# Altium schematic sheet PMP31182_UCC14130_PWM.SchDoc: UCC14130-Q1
size A3
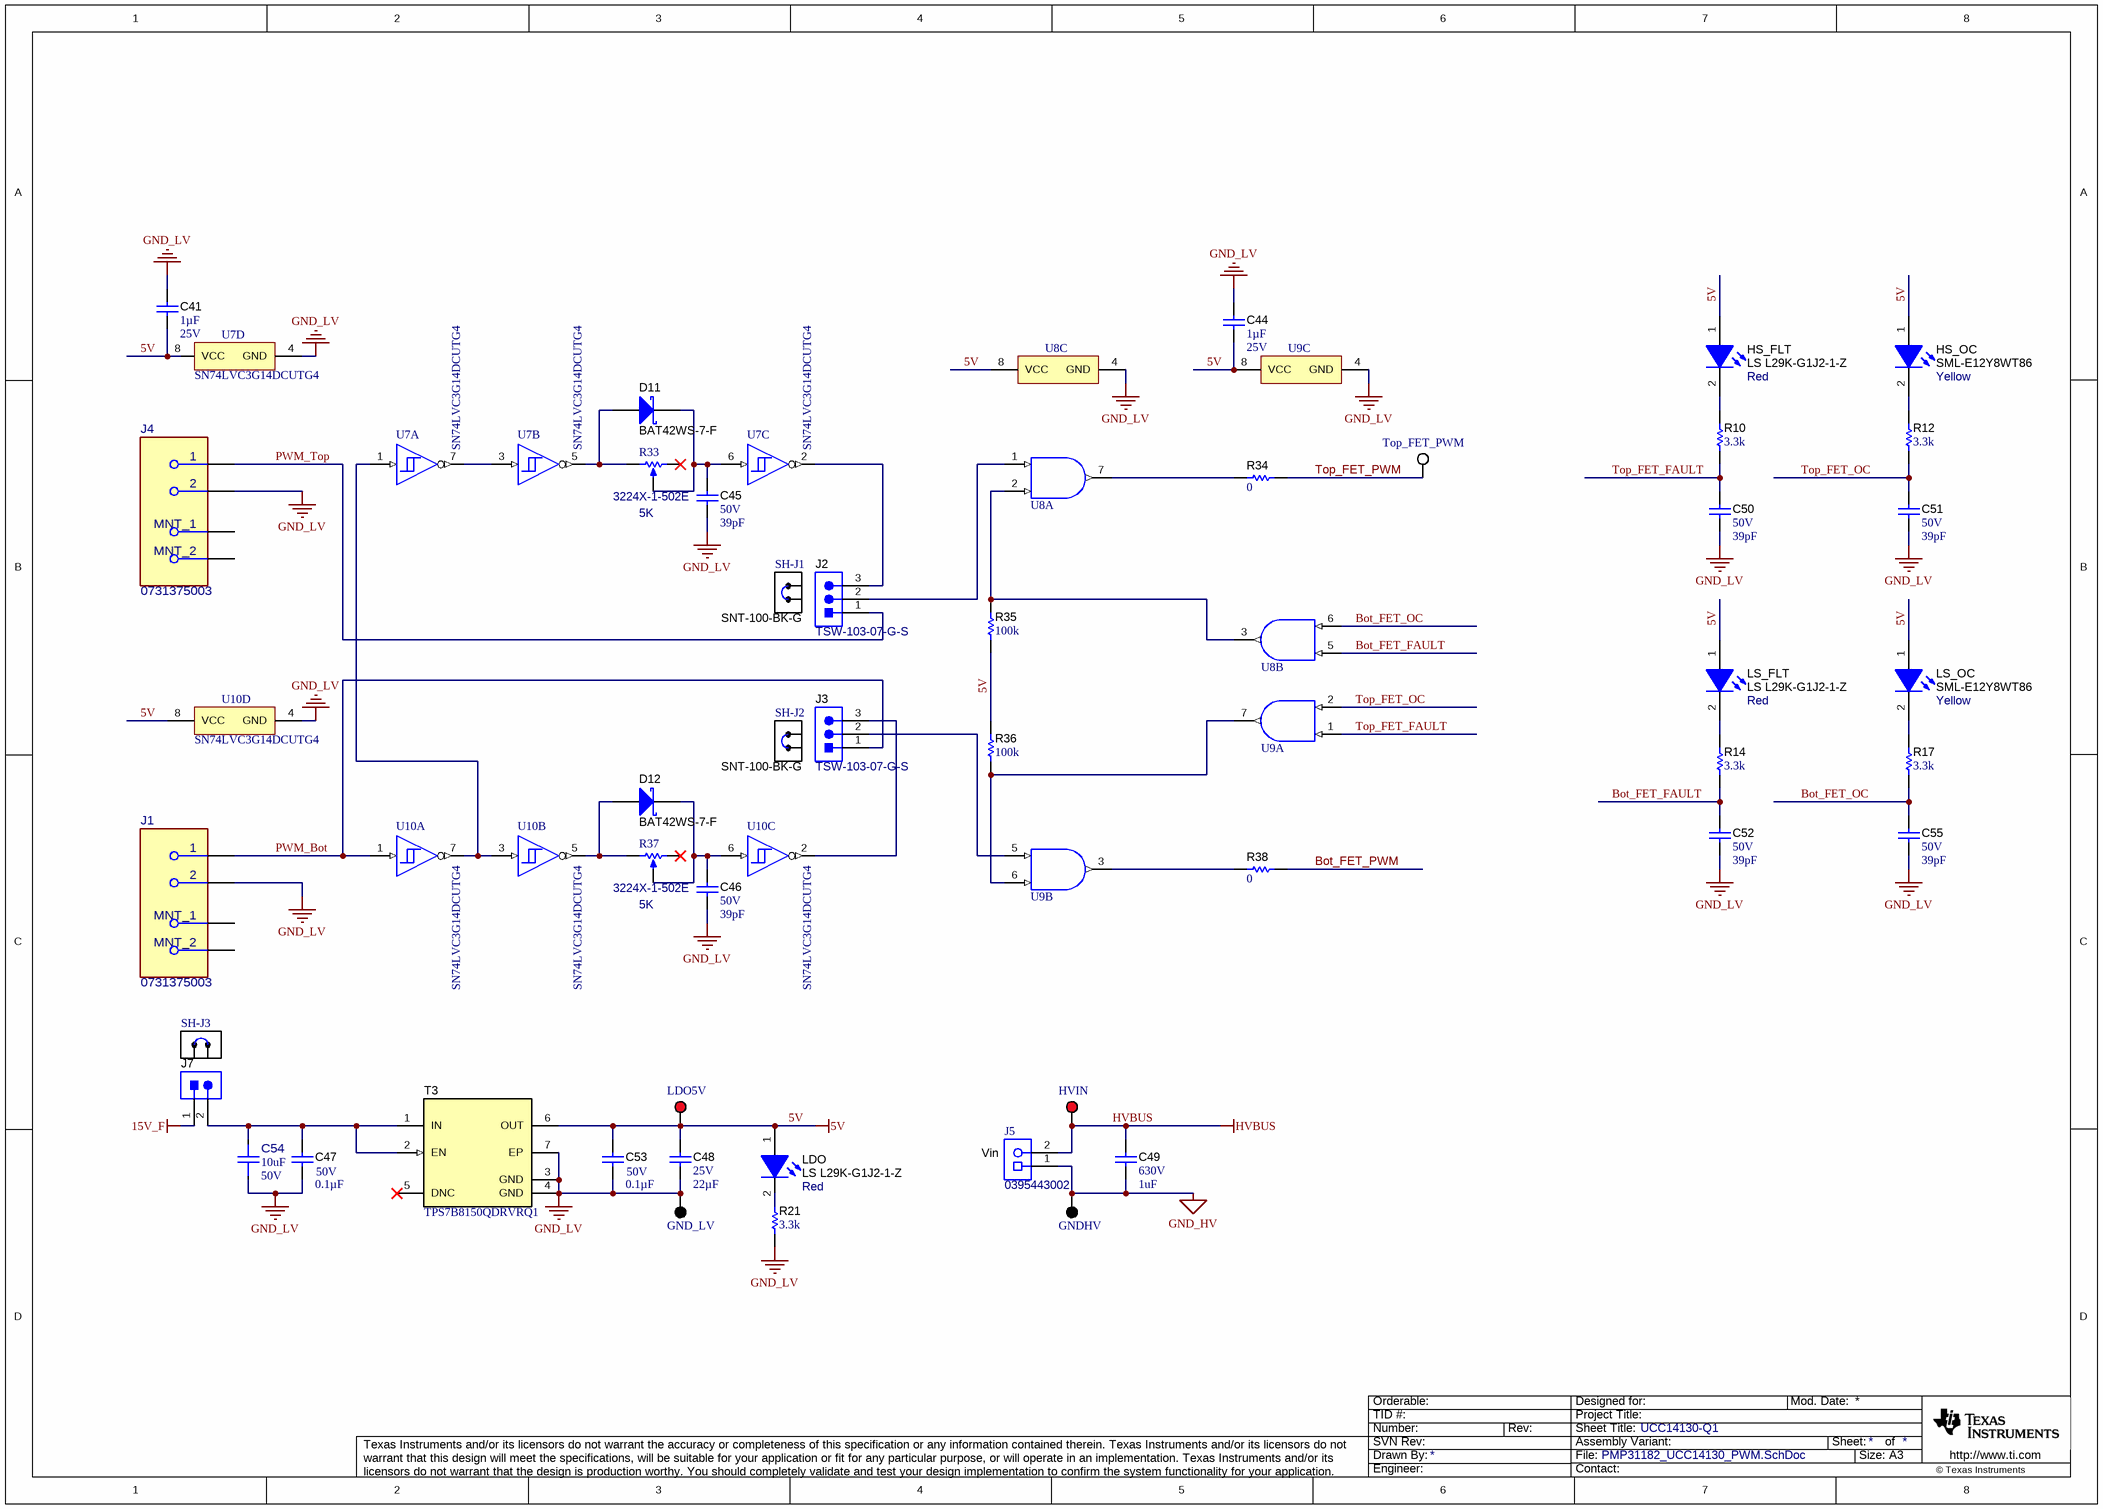
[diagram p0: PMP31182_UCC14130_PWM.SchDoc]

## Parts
C41  Cap_F: 1µF  VDC_V: 25V  [0603]  (hidden comment: CGA3E1X7R1E105K080AD)
C44  Cap_F: 1µF  VDC_V: 25V  [0603]  (hidden comment: CGA3E1X7R1E105K080AD)
C45  VDC_V: 50V  ValueDisplayed: 39pF  [0603]  (hidden comment: GRM1885C1H390JA01D)
C46  VDC_V: 50V  ValueDisplayed: 39pF  [0603]  (hidden comment: GRM1885C1H390JA01D)
C47  VDC_V: 50V  ValueDisplayed: 0.1µF  [0603]  (hidden comment: CGA3E3X8R1H104K080AE)
C48  VDC_V: 25V  ValueDisplayed: 22µF  [1210_270]  (hidden comment: GRT32ER61E226KE13L)
C49  VDC_V: 630V  ValueDisplayed: 1uF  [2220_450]  (hidden comment: 2220Y6300105KETWS2)
C50  VDC_V: 50V  ValueDisplayed: 39pF  [0603]  (hidden comment: GRM1885C1H390JA01D)
C51  VDC_V: 50V  ValueDisplayed: 39pF  [0603]  (hidden comment: GRM1885C1H390JA01D)
C52  VDC_V: 50V  ValueDisplayed: 39pF  [0603]  (hidden comment: GRM1885C1H390JA01D)
C53  VDC_V: 50V  ValueDisplayed: 0.1µF  [0603]  (hidden comment: CGA3E3X8R1H104K080AE)
C54  ValueDisplayed: 10uF  VDC_V: 50V  [FP-UMK325AB7106KMHP_1210-MFG]  (hidden comment: UMK325AB7106KMHP)
C55  VDC_V: 50V  ValueDisplayed: 39pF  [0603]  (hidden comment: GRM1885C1H390JA01D)
D11  BAT42WS-7-F  [SOD-323]
D12  BAT42WS-7-F  [SOD-323]
GND_LV  5006  [Keystone5006]  (value not drawn)
GNDHV  5006  [Keystone5006]  (value not drawn)
HS_FLT  LS L29K-G1J2-1-Z  value Red  [LS L29K_Red]
HS_OC  SML-E12Y8WT86  value Yellow  [SML-E1_Yellow]
HVIN  5005  [Keystone5005]  (value not drawn)
J1  0731375003  [FP-0731375003_CONN_BNC_RCPT-MFG]
J2  TSW-103-07-G-S  [TSW-103-07-G-S]
J3  TSW-103-07-G-S  [TSW-103-07-G-S]
J4  0731375003  [FP-0731375003_CONN_BNC_RCPT-MFG]
J5  0395443002  [Molex_0395443002]
J7  TSW-102-07-G-S  [TSW-102-07-G-S]  (value not drawn)
LDO  LS L29K-G1J2-1-Z  value Red  [LS L29K_Red]
LDO5V  5005  [Keystone5005]  (value not drawn)
LS_FLT  LS L29K-G1J2-1-Z  value Red  [LS L29K_Red]
LS_OC  SML-E12Y8WT86  value Yellow  [SML-E1_Yellow]
R10  ValueDisplayed: 3.3k  [0603]  (hidden comment: CRCW06033K30JNEA)
R12  ValueDisplayed: 3.3k  [0603]  (hidden comment: CRCW06033K30JNEA)
R14  ValueDisplayed: 3.3k  [0603]  (hidden comment: CRCW06033K30JNEA)
R17  ValueDisplayed: 3.3k  [0603]  (hidden comment: CRCW06033K30JNEA)
R21  ValueDisplayed: 3.3k  [0603]  (hidden comment: CRCW06033K30JNEA)
R33  3224X-1-502E  value 5K  [TRIM_3224X]
R34  ValueDisplayed: 0  [0603_HV]  (hidden comment: CRCW06030000Z0EA)
R35  ValueDisplayed: 100k  [0603]  (hidden comment: CRCW0603100KJNEAC)
R36  ValueDisplayed: 100k  [0603]  (hidden comment: CRCW0603100KJNEAC)
R37  3224X-1-502E  value 5K  [TRIM_3224X]
R38  ValueDisplayed: 0  [0603_HV]  (hidden comment: CRCW06030000Z0EA)
SH-J1  SNT-100-BK-G  [SNT-100-BK-G]
SH-J2  SNT-100-BK-G  [SNT-100-BK-G]
SH-J3  SNT-100-BK-G  [SNT-100-BK-G]  (value not drawn)
T3  TPS7B8150QDRVRQ1  [DRV0006A]
Top_FET_PWM  5007  [Keystone5007]  (value not drawn)
U7  SN74LVC3G14DCUTG4  [DCU0008A_N]  (parts A,B,C,D of 4)
U8  SN74LVC2G08IDCTRQ1  [DCT0008A_N]  (value not drawn)  (parts A,B,C of 3)
U9  SN74LVC2G08IDCTRQ1  [DCT0008A_N]  (value not drawn)  (parts A,B,C of 3)
U10  SN74LVC3G14DCUTG4  [DCU0008A_N]  (parts A,B,C,D of 4)

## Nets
5V: C41.2 C44.2 C48.1 C53.1 HS_FLT.1(A) HS_OC.1(A) LDO.1(A) LDO5V.1 LS_FLT.1(A) LS_OC.1(A) R35.1 R36.2 T3.6(OUT) U7.8(VCC) U8.8(VCC) U9.8(VCC) U10.8(VCC)
15V_F: J7.1
GND_HV: C49.2 GNDHV.1 J5.1
GND_LV: C41.1 C44.1 C45.2 C46.2 C47.2 C48.2 C50.2 C51.2 C52.2 C53.2 C54.1 C55.2 GND_LV.1 J1.2 J4.2 R21.1 T3.3(GND) T3.4(GND) T3.7(EP) U7.4(GND) U8.4(GND) U9.4(GND) U10.4(GND)
HVBUS: C49.1 HVIN.1 J5.2
Bot_FET_FAULT: C52.1 R14.1 U8.5(2A)
Bot_FET_OC: C55.1 R17.1 U8.6(2B)
Bot_FET_PWM: R38.2
PWM_Bot: J1.1 J3.1 U10.1(1A)
PWM_Top: J2.1 J4.1
Top_FET_FAULT: C50.1 R10.1 U9.1(1A)
Top_FET_OC: C51.1 R12.1 U9.2(1B)
Top_FET_PWM: R34.2 Top_FET_PWM.1
NetC45_1: C45.1 D11.1(K) R33.2(WIPER) U7.6(3A)
NetC46_1: C46.1 D12.1(K) R37.2(WIPER) U10.6(3A)
NetC47_1: C47.1 C54.2 J7.2 T3.1(IN) T3.2(EN)
NetD11_2: D11.2(A) R33.1(CCW) U7.5(2Y)
NetD12_2: D12.2(A) R37.1(CCW) U10.5(2Y)
NetHS_FLT_2: HS_FLT.2(K) R10.2
NetHS_OC_2: HS_OC.2(K) R12.2
NetJ2_2: J2.2 U8.1(1A)
NetJ2_3: J2.3 U7.2(3Y)
NetJ3_2: J3.2 U9.5(2A)
NetJ3_3: J3.3 U10.2(3Y)
NetLDO_2: LDO.2(K) R21.2
NetLS_FLT_2: LS_FLT.2(K) R14.2
NetLS_OC_2: LS_OC.2(K) R17.2
NetR34_1: R34.1 U8.7(1Y)
NetR35_2: R35.2 U8.2(1B) U8.3(2Y)
NetR36_1: R36.1 U9.6(2B) U9.7(1Y)
NetR38_1: R38.1 U9.3(2Y)
NetU7_1: U7.1(1A) U10.3(2A) U10.7(1Y)
NetU7_3: U7.3(2A) U7.7(1Y)

Not connected (* = marked no-connect by the designer): J1 3(MNT_1) 4(MNT_2); J4 3(MNT_1) 4(MNT_2); R33 3(CW)*; R37 3(CW)*; T3 5(DNC)*

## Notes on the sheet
- (near J5) Vin

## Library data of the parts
C41 C44 = CMP-0082523-1: CAP, CERM, 1 µF, 25 V,+/- 10%, X7R, AEC-Q200 Grade 1, 0603; Manufacturer: TDK; SizeAreaWB_mm2: 4.68; SizeArea_mm2: 1.28; AEC Qualified: Y; AEC Category: Q200; Value: 1uF; TaMax_C: 125°C; SizeZ_mm: 1; Polarized: N; TaMin_C: -55°C; SizeY_mm: 0.8; U/M: EA; SizeX_mm: 1.6
C45 C46 C50-C52 C55 = CMP-0007214-4: CAP, CERM, 39 pF, 50 V, +/- 5%, C0G/NP0, 0603; Manufacturer: MuRata; TaMin_C: -55°C; Polarized: N; SizeAreaWB_mm2: 4.68; Value1: Unknown; U/M: EA; Value: 39pF; TaMax_C: 125°C; SizeZ_mm: 1; SizeX_mm: 1.6; SizeY_mm: 0.8; SizeArea_mm2: 1.28; AEC Category: Q200
C47 C53 = CMP-0079911-1: CAP, CERM, 0.1 µF, 50 V,+/- 10%, X8R, AEC-Q200 Grade 0, 0603; Manufacturer: TDK; Cap_F: 100nF; SizeAreaWB_mm2: 4.68; SizeArea_mm2: 1.28; AEC Qualified: Y; AEC Category: Q200; Value: 0.1uF; TaMax_C: 150°C; SizeZ_mm: 1; AEC Grade: 0; Polarized: N; TaMin_C: -55°C; SizeY_mm: 0.8; U/M: EA; SizeX_mm: 1.6
C48 = CMP-0084059-1: CAP, CERM, 22 µF, 25 V,+/- 10%, X5R, AEC-Q200 Grade 3, 1210; Manufacturer: MuRata; SizeAreaWB_mm2: 14.7; SizeArea_mm2: 8; AEC Qualified: Y; AEC Category: Q200; Value: 22uF; TaMax_C: 85°C; SizeZ_mm: 2.7; AEC Grade: 3; Polarized: N; TaMin_C: -55°C; SizeY_mm: 2.5; U/M: EA; SizeX_mm: 3.2; Cap_Case: 1210
C49 = CMP-0064919-2: CAP, CERM, 1 uF, 630 V,+/- 10%, X7R, AEC-Q200 Grade 1, 2220; Manufacturer: Knowles Capacitors; PartNumber: 2220Y6300105KXTWS2; TaMin_C: -55°C; Polarized: N; SizeAreaWB_mm2: 53.9; Value1: Unknown; U/M: EA; Value: 1uF; TaMax_C: 125°C; SizeZ_mm: 4.5; SizeX_mm: 5.7; SizeY_mm: 5; Cap_Case: 2220; SizeArea_mm2: 28.5; AEC Qualified: Y; Cap_F: 1µF; AEC Grade: 1; AEC Category: Q200
C54 = CMP-0089980-1: 10µF ±10% 50V Ceramic Capacitor X7R 1210 (3225 Metric); Manufacturer: Taiyo Yuden; SizeZ_mm: 2.8mm; AEC Qualified: Yes; AEC Grade: Grade 1; TempCo: 15%
D11 D12 = CMP-0028447-2: Diode, Schottky, 30 V, 0.2 A, SOD-323; Manufacturer: Diodes Inc.; SizeZ_mm: 1; AEC Category: Q101; Green_REACh: Incomplete; Green_Lifecycle: Not Set; Vr_V: 30V; Vf_V: 1V; Io_A: 200mA; SizeY_mm: 1.35; Value1: 0.2A; Value: 30V; SizeArea_mm2: 3.645; SizeX_mm: 2.7; SizeAreaWB_mm2: 8.695
GND_LV GNDHV = CMP-0055143-1: Test Point, Compact, Black, TH; Manufacturer: Keystone; CNHeader: FALSE; Green_Lifecycle: Active; Green_REACh: Passed; ContactFinish: Silver; CT: TRUE
HS_FLT LDO LS_FLT = CMP-0002902-2: LED, Red, SMD; Manufacturer: OSRAM; Io_A: 20mA; Vr_V: 12V; Tjmax_C: 110°C; Value1: W; Angle: 160; Vf_V: 1.8V
HS_OC LS_OC = CMP-0002977-1: LED, Yellow, SMD; Manufacturer: Rohm; Io_A: 20mA; Power_TotalModule: 54mW; Vr_V: 5V; Tjmax_C: 85°C; Value1: 0.054W; U/M: EA; Ir_A: 10µA; Vf_V: 2.2V; LuminousIntensity_IV: 63
HVIN LDO5V = CMP-0055142-1: Test Point, Compact, Red, TH; Manufacturer: Keystone; CNHeader: FALSE; Green_Lifecycle: Active; Green_REACh: Passed; ContactFinish: Silver; CT: TRUE
J1 J4 = CMP-0095823-1: Connector BNC Female 0Hz To 2GHz 50 Ohm Solder Right Angle Through Hole Gold Tray; Manufacturer: Molex; Voltage_V: 500V; Impedance: 50Ω; Standoff Height: 0.57mm; Is Female: yes; ContactFinish: Gold,Tin,Nickel; Dielectric Material: Polypropylene; SizeZ_mm: 13.33mm; AEC Qualified: No
J2 J3 = CMP-0075407-2: Header, 100mil, 3x1, Gold, TH; Manufacturer: Samtec; Pitch_mm: 2.54; Cert_VDE: N; Gender: Male; Cert_CSA: Y; Voltage_V: 550V; Green_REACh: Passed; Current_A: 6.3A; Green_Lifecycle: Active; Row_Count: 1
J5 = CMP-0055342-2: Terminal Block, 5.08mm, 2x1, TH; Manufacturer: Molex; Current_A: 15A; Green_Lifecycle: Not Set; Gender: Female; Green_REACh: Incomplete; Voltage_V: 300V; Row_Count: 1; Pitch_mm: 5.08
J7 = CMP-0075405-2: Header, 100mil, 2x1, Gold, TH; Manufacturer: Samtec; Pitch_mm: 2.54; Cert_VDE: N; Gender: Male; Cert_CSA: Y; Voltage_V: 550V; Green_REACh: Passed; Current_A: 6.3A; Green_Lifecycle: Active; Row_Count: 1
R10 R12 R14 R17 R21 = CMP-0025797-4: RES, 3.3 k, 5%, 0.1 W, AEC-Q200 Grade 0, 0603; Manufacturer: Vishay-Dale; Power_W: 100mW; TempCo: 200 ppm/C; Value_Code: 3k30; Value: 3.3k; EIA_Code: E24; SizeX_mm: 1.6; SizeY_mm: 0.8; SizeZ_mm: 1; Value2: 0.1W; SizeArea_mm2: 1.28; AEC Qualified: Y; VDC_V: 75V; AEC Category: Q200; AEC Grade: 0
R33 R37 = CMP-0002062-2: Trimmer, 5 K, 0.25 W, SMD; Manufacturer: Bourns
R34 R38 = CMP-0025697-4: RES, 0, 5%, 0.1 W, AEC-Q200 Grade 0, 0603; Manufacturer: Vishay-Dale; Power_W: 100mW; TempCo: 200 ppm/C; Value_Code: 0000; Value: 0; EIA_Code: E24; SizeX_mm: 1.6; SizeY_mm: 0.8; SizeZ_mm: 1; Value2: 0.1W; SizeArea_mm2: 1.28; AEC Qualified: Y; VDC_V: 75V; AEC Category: Q200
R35 R36 = CMP-0082530-1: RES, 100 k, 5%, 0.1 W, 0603; Manufacturer: Vishay-Dale; Power_W: 100mW; TempCo: 200 ppm/C; SizeAreaWB_mm2: 4.68; Value: 100k; EIA_Code: E24; SizeX_mm: 1.6; SizeY_mm: 0.8; SizeZ_mm: 1; Value2: 0.1W; SizeArea_mm2: 1.28; AEC Qualified: N; VDC_V: 75V; AEC Category: Q200
SH-J1-SH-J3 = CMP-0003623-3: Shunt, 100mil, Gold plated, Black; Alternate PartNumber: 969102-0000-DA; Manufacturer: Samtec; Alternate Manufacturer: 3M; Value: 1x2
T3 = CMP-0086086-2: 150-mA High-Voltage Ultralow-IQ Low-Dropout Regulator, DRV0006A (WSON-6); Alternate Manufacturer: Texas Instruments; AEC Category: Q200; CompType: IC; SizeArea_mm2: 4; SizeY_mm: 2; SizeAreaWB_mm2: 9; AEC Qualified: Y; SizeZ_mm: 0.8
Top_FET_PWM = CMP-0055144-1: Test Point, Compact, White, TH; Manufacturer: Keystone; CNHeader: FALSE; Green_Lifecycle: Active; Green_REACh: Passed; ContactFinish: Silver; CT: TRUE
U7 U10 = CMP-0051969-2: Triple Schmitt-Trigger Inverter, DCU0008A (VSSOP-8); Manufacturer: Texas Instruments; Output Type: CMOS; Logic: Inverting; tpd @ Nom Voltage(Max)(ns): 9.2,5.7,5.4,4.3; Bits(#): 3; ICC @ Nom Voltage(Max)(mA): 0.01; Output Drive (IOL/IOH)(Max)(mA): 32/-32; F @ Nom Voltage(Max)(Mhz): 150; Voltage(Nom)(V): 1.8,2.5,3.3,5; Input Type: CMOS/TTL; Schmitt Trigger: Yes; VCC(Max)(V): 5.5; VCC(Min)(V): 1.65; Technology Family: LVC; Rating: Catalog; 3-State Output: No; AEC Category: Q200; AEC Qualified: N; CompType: IC; SizeAreaWB_mm2: 12.6; SizeArea_mm2: 6.4; SizeX_mm: 3.2; SizeY_mm: 2.0; SizeZ_mm: 0.9
U8 U9 = CMP-0051803-1: Automotive Catalog Dual 2-Input Positive-AND Gate, DCT0008A, LARGE T&R; Manufacturer: Texas Instruments; Generic Part Number: SN74LVC2G08-Q1; F @ Nom Voltage(Max)(Mhz): 150; ICC @ Nom Voltage(Max)(mA): 0.01; Input Type: CMOS/TTL; Output Type: CMOS; Logic: True; VCC(Max)(V): 5.5; Technology Family: LVC; Schmitt Trigger: No; Bits(#): 2; tpd @ Nom Voltage(Max)(ns): 9,5.1,4.7,3.8; VCC(Min)(V): 1.65; Voltage(Nom)(V): 1.8,2.5,3.3,5; Output Drive (IOL/IOH)(Max)(mA): 32/-32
